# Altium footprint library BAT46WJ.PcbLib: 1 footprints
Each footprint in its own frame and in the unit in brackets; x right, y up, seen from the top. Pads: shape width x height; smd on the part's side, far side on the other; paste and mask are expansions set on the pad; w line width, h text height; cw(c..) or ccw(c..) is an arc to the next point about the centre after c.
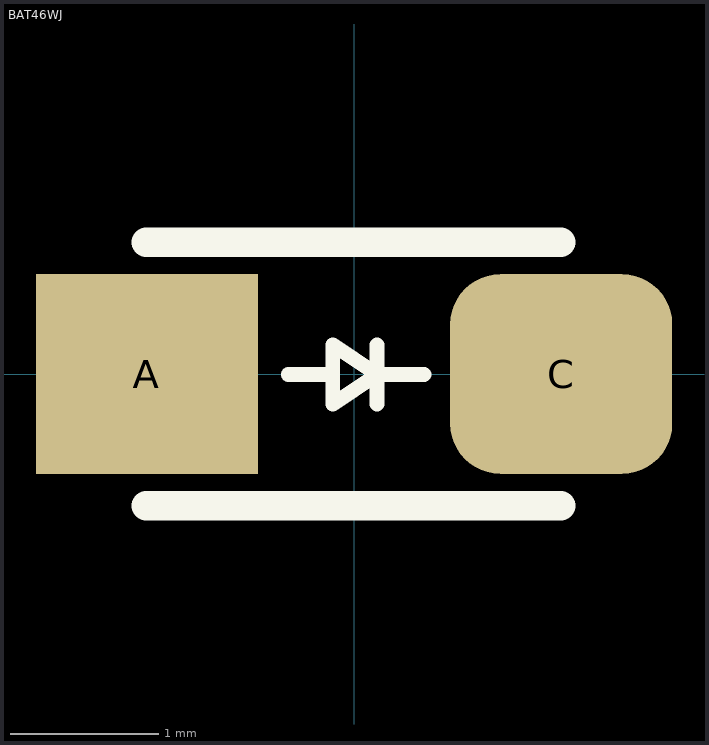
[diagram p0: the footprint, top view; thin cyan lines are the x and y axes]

## BAT46WJ [mm]
pads (2):
  rect 1.5x1.35 smd: A(-1.4,0)
  rrect50% 1.5x1.35 smd: C(1.4,0)
Top Overlay:
  lines w0.1: -0.444,-0.003 -0.144,-0.003 ; 0.156,-0.203 0.156,0.197 ; 0.172,-0.003 0.472,-0.003 ; -0.144,-0.203 0.156,-0.003 -0.144,0.197 -0.144,-0.203
  lines w0.2: -1.403,-0.889 1.397,-0.889 ; -1.403,0.889 1.397,0.889
3D body "BAT46WJF.STEP": height 1.45, standoff 0, extent -1.952,-0.775 1.698,0.775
